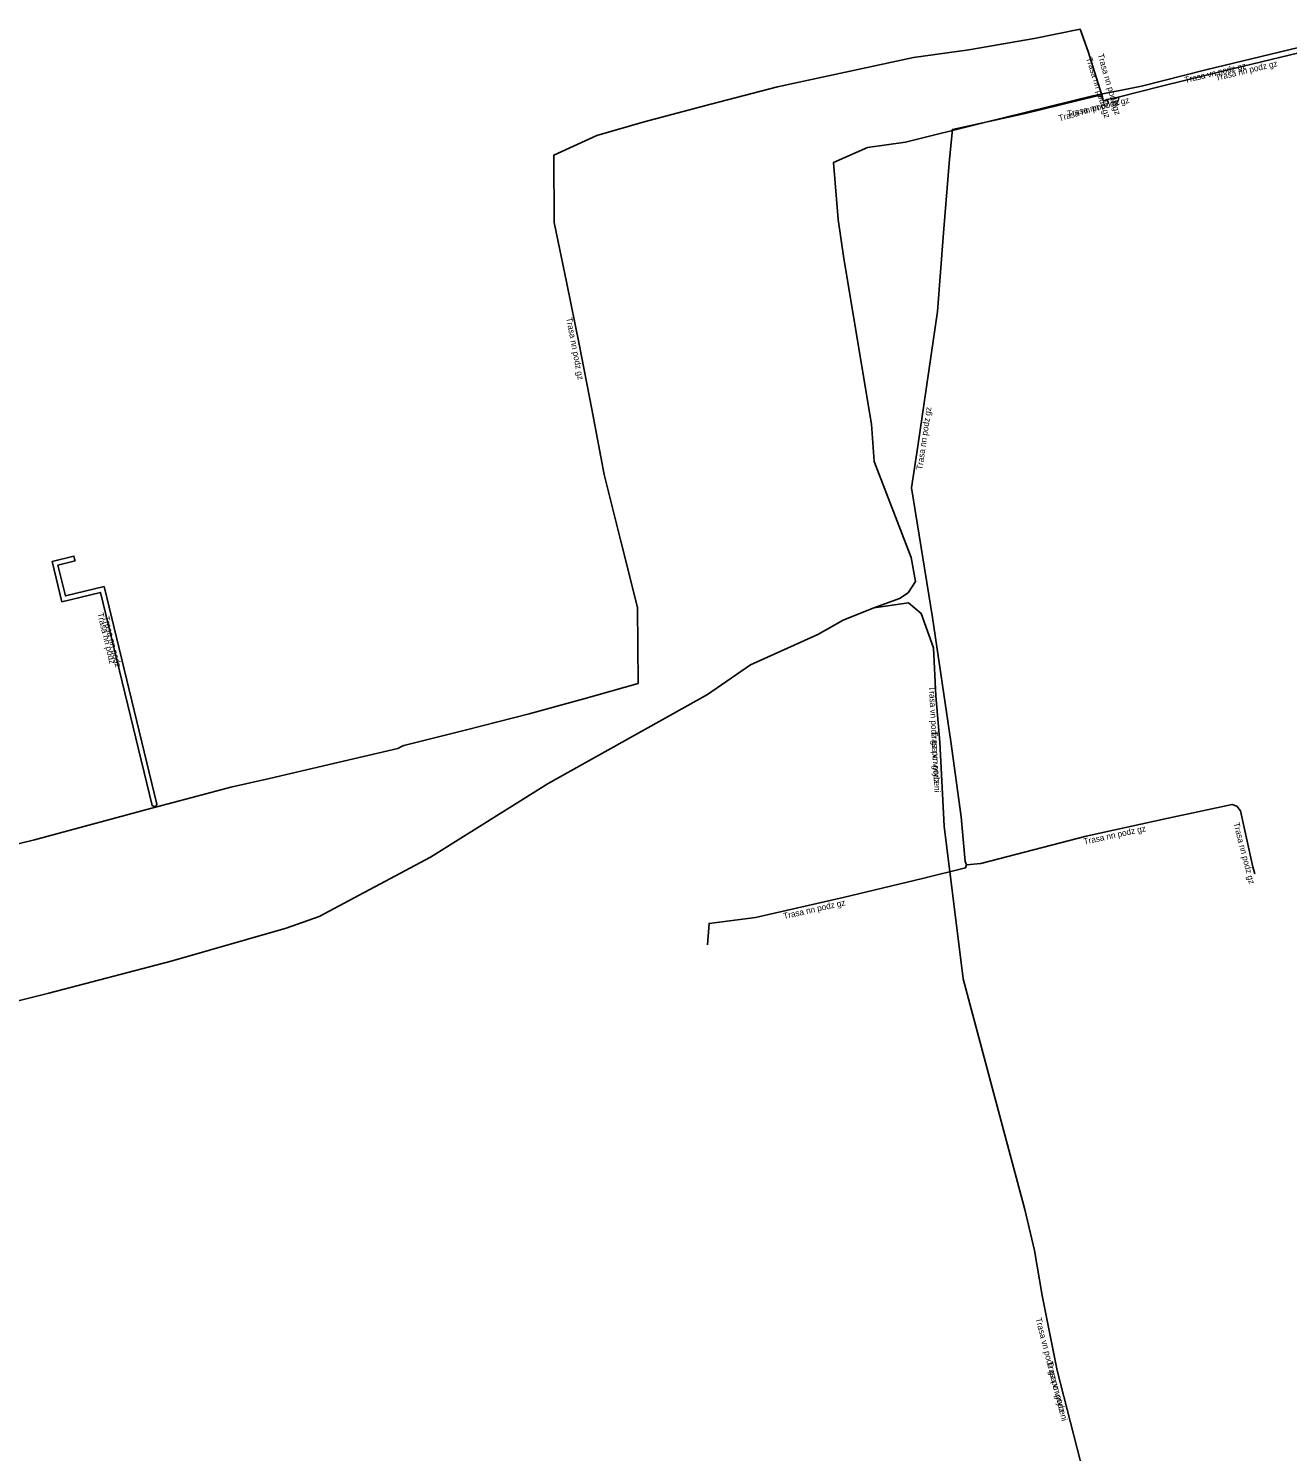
# Model space of a CAD drawing. Extents: x -473162 to -472629, y -1107202 to -1106680.
# Drawn here: x -472793.2 to -472690.6, y -1107053.9 to -1106938 of the extents above; entities that cross this region are included whole.
import ezdxf

# ---------------------------------------------------------------- set-up
doc = ezdxf.new("R2010")
doc.units = 0
for name, color, linetype in [('Popiskový text - Ostatní atributy Trasy', 7, 'Continuous'), ('Spojnice NN', 7, 'Continuous'), ('Spojnice VN', 7, 'Continuous')]:
    doc.layers.add(name, color=color, linetype=linetype)

msp = doc.modelspace()

# ---------------------------------------------------------------- linework, layer by layer
at = {"layer": 'Spojnice NN'}
for points in [[(-472705.66, -1106943.55), (-472706.17, -1106941.92), (-472706.82, -1106939.84), (-472707.48, -1106938.03), (-472711.22, -1106938.77), (-472713.88, -1106939.23), (-472716.54, -1106939.7), (-472721.04, -1106940.33), (-472726.59, -1106941.53), (-472732.13, -1106942.72), (-472737.57, -1106944.14), (-472743.01, -1106945.56), (-472746.85, -1106946.69), (-472750.35, -1106948.28), (-472750.32, -1106953.77), (-472749.3, -1106958.73), (-472748.29, -1106963.68), (-472747.27, -1106968.99), (-472746.26, -1106974.3), (-472744.9, -1106979.72), (-472743.54, -1106985.14), (-472743.51, -1106988.23), (-472743.49, -1106991.32), (-472747.92, -1106992.57), (-472752.36, -1106993.81), (-472757.48, -1106995.09), (-472762.59, -1106996.37), (-472762.76, -1106996.47), (-472763.08, -1106996.62), (-472768.31, -1106997.85), (-472773.54, -1106999.07), (-472775.11, -1106999.41), (-472776.67, -1106999.76), (-472779.95, -1107000.64), (-472782.82, -1107001.41)], [(-472681.06, -1106937.96), (-472684.53, -1106938.75), (-472688.19, -1106939.59), (-472692.7, -1106940.68), (-472697.2, -1106941.76), (-472700.84, -1106942.67), (-472704.37, -1106943.56)], [(-472716.74, -1107006.11), (-472716.83, -1107005.83), (-472717.16, -1107002.19), (-472718.02, -1106996.06), (-472719.5, -1106985.95), (-472721.21, -1106975.38), (-472720.7, -1106971.99), (-472719.1, -1106961.02), (-472718.6, -1106954.62), (-472718.11, -1106948.61), (-472717.88, -1106946.18), (-472711.96, -1106944.89), (-472706.08, -1106943.46), (-472705.66, -1106943.55)], [(-472705.26, -1106943.76), (-472705.38, -1106943.79), (-472705.6, -1106943.85), (-472705.66, -1106943.55)], [(-472704.37, -1106943.56), (-472704.47, -1106943.58), (-472705.26, -1106943.76)], [(-472705.17, -1106944.05), (-472705.26, -1106943.76)], [(-472704.32, -1106943.74), (-472704.37, -1106943.56)], [(-472789.41, -1106981.16), (-472789.46, -1106980.95), (-472791.25, -1106981.39), (-472790.45, -1106984.67), (-472787.3, -1106983.91), (-472783.1, -1107001.28), (-472782.82, -1107001.41)], [(-472789.41, -1106981.16), (-472789.37, -1106981.34), (-472790.77, -1106981.68), (-472790.16, -1106984.19), (-472787.01, -1106983.43), (-472782.71, -1107001.17), (-472782.82, -1107001.41)], [(-472782.82, -1107001.41), (-472783.23, -1107001.52), (-472787.95, -1107002.79), (-472792.68, -1107004.07), (-472798.83, -1107005.56), (-472804.97, -1107007.06), (-472813.17, -1107009.02), (-472818.5, -1107010.4), (-472823.83, -1107011.78), (-472830.09, -1107013.63)], [(-472716.74, -1107006.11), (-472715.55, -1107005.99), (-472706.98, -1107003.76), (-472700.31, -1107002.3), (-472695.09, -1107001.18), (-472694.71, -1107001.31), (-472694.41, -1107001.71), (-472693.5, -1107005.78)], [(-472737.84, -1107012.63), (-472737.71, -1107010.87), (-472733.92, -1107010.39), (-472726.79, -1107008.77), (-472720.31, -1107007.21), (-472716.81, -1107006.35), (-472716.74, -1107006.11)], [(-472693.5, -1107005.78), (-472693.39, -1107006.27), (-472693.24, -1107006.84)]]:
    msp.add_lwpolyline(points, dxfattribs=at)
at = {"layer": 'Spojnice VN'}
for points in [[(-472724.29, -1106985.16), (-472722.19, -1106984.41), (-472721.49, -1106983.94), (-472720.89, -1106983.03), (-472721.25, -1106981.06), (-472724.26, -1106973.25), (-472724.48, -1106970.21), (-472726.72, -1106956.69), (-472727.2, -1106953.53), (-472727.57, -1106948.89), (-472724.8, -1106947.66), (-472721.7, -1106947.22), (-472715.48, -1106945.68), (-472706.43, -1106943.46), (-472702.47, -1106942.65), (-472697.23, -1106941.34), (-472688.2, -1106939.17)], [(-472875.93, -1107028.1), (-472871, -1107031.82), (-472861.33, -1107033.12), (-472850.8, -1107030.64), (-472845.32, -1107029.36), (-472833.57, -1107026.45), (-472822.85, -1107023.72), (-472815.1, -1107022.25), (-472801.34, -1107019), (-472791.51, -1107016.55), (-472781.55, -1107013.95), (-472772.18, -1107011.27), (-472769.48, -1107010.31), (-472760.41, -1107005.48), (-472750.82, -1106999.47), (-472737.83, -1106992.21), (-472734.32, -1106989.81), (-472728.85, -1106987.34), (-472726.78, -1106986.17), (-472724.29, -1106985.16)], [(-472875.93, -1107028.1), (-472871, -1107031.82), (-472861.33, -1107033.12), (-472850.8, -1107030.64), (-472845.32, -1107029.36), (-472833.57, -1107026.45), (-472822.85, -1107023.72), (-472815.1, -1107022.25), (-472801.34, -1107019), (-472791.51, -1107016.55), (-472781.55, -1107013.95), (-472772.18, -1107011.27), (-472769.48, -1107010.31), (-472760.41, -1107005.48), (-472750.82, -1106999.47), (-472737.83, -1106992.21), (-472734.32, -1106989.81), (-472728.85, -1106987.34), (-472726.78, -1106986.17), (-472724.29, -1106985.16)], [(-472724.29, -1106985.16), (-472721.45, -1106984.75), (-472720.42, -1106985.62), (-472719.42, -1106988.41), (-472719.22, -1106992.33), (-472718.91, -1106996.12), (-472718.55, -1107002.96), (-472716.99, -1107015.39)], [(-472724.29, -1106985.16), (-472721.45, -1106984.75), (-472720.42, -1106985.62), (-472719.42, -1106988.41), (-472719.22, -1106992.33), (-472718.91, -1106996.12), (-472718.55, -1107002.96), (-472716.99, -1107015.39)], [(-472716.99, -1107015.39), (-472713.58, -1107028.2), (-472711.99, -1107034.19), (-472711.18, -1107037.52), (-472710.57, -1107041.2), (-472709.35, -1107047.29), (-472706.66, -1107057.79), (-472706.42, -1107059.68), (-472705.88, -1107060.98), (-472704.76, -1107062.02), (-472702.92, -1107061.3), (-472701.04, -1107059.76), (-472700.08, -1107059.45), (-472699.31, -1107059.75), (-472698.84, -1107060.35), (-472698.28, -1107062.71), (-472698.29, -1107065.09), (-472699.21, -1107067.02), (-472697.09, -1107074.55)], [(-472716.99, -1107015.39), (-472713.58, -1107028.2), (-472711.99, -1107034.19), (-472711.18, -1107037.52), (-472710.57, -1107041.2), (-472709.35, -1107047.29), (-472706.66, -1107057.79), (-472706.42, -1107059.68), (-472705.88, -1107060.98), (-472704.76, -1107062.02), (-472702.92, -1107061.3), (-472701.04, -1107059.76), (-472700.08, -1107059.45), (-472699.31, -1107059.75), (-472698.84, -1107060.35), (-472698.28, -1107062.71), (-472698.29, -1107065.09), (-472699.21, -1107067.02), (-472697.09, -1107074.55)]]:
    msp.add_lwpolyline(points, dxfattribs=at)

# ---------------------------------------------------------------- texts
at = {"layer": 'Popiskový text - Ostatní atributy Trasy'}
for s, rotation, p in [('Trasa nn podz gz', 287.2289, (-472706.99, -1106940.38)), ('Trasa nn podz gz', 286.1151, (-472706.05, -1106940.09)), ('Trasa vn podz gz', 13.5125, (-472698.89, -1106942.41)), ('Trasa nn podz gz', 13.5356, (-472696.37, -1106942.23)), ('Trasa nn podz gz', 15.8071, (-472709.15, -1106945.53)), ('Trasa nn podz gz', 12.8558, (-472708.46, -1106945.16)), ('Trasa nn podz gz', 280.8467, (-472749.36, -1106961.55)), ('Trasa nn podz gz', 81.709, (-472720.33, -1106973.95)), ('Trasa nn podz', 283.6194, (-472787.56, -1106985.62)), ('Trasa nn podz', 283.6207, (-472787.08, -1106985.9)), ('Trasa vn podz gz po vytyceni', 272.9732, (-472719.79, -1106991.56)), ('Trasa vn podz', 272.9732, (-472719.6, -1106995.24)), ('Trasa nn podz gz', 12.3468, (-472707.13, -1107004.46)), ('Trasa nn podz gz', 284.559, (-472694.99, -1107002.71)), ('Trasa nn podz gz', 12.7665, (-472731.6, -1107010.53)), ('Trasa vn podz gz po vytyceni', 284.3952, (-472711.11, -1107043.07)), ('Trasa vn podz', 284.3952, (-472710.19, -1107046.64))]:
    msp.add_text(s, height=0.5, rotation=rotation, dxfattribs=at).set_placement(p)

doc.saveas('drawing.dxf')
